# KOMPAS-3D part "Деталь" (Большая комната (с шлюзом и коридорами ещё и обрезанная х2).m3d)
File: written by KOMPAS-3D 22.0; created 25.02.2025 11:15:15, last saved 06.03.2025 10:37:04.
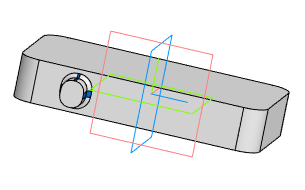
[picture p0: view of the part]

Document properties: Автор: Пользователь Windows; Полное имя файла: C:\Users\Student\Documents\Картошечка\База Сабнатика\Большая комната\Большая комната (с шлюзом и коридорами ещё и обрезанная х2).m3d

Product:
- Part/product: Деталь
    Масса: 1.391303

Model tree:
1. Эскиз:1
2. Элемент выдавливания:1
     Расстояние 1 = 35
3. Скругление:2  (with: Элемент выдавливания:1)
     Радиус = 10
4. Скругление:1  (with: Элемент выдавливания:1)
     Радиус = 7
5. Эскиз:4  (with: Элемент выдавливания:1)
6. Элемент выдавливания:4
     Расстояние 1 = 10
7. Скругление:6  (with: Элемент выдавливания:4)
     Радиус = 2
8. Эскиз:5  (with: Элемент выдавливания:1)
9. Элемент выдавливания:5
     Расстояние 1 = 10
10. Скругление:7  (with: Элемент выдавливания:5)
     Радиус = 2
11. Эскиз:6  (with: Элемент выдавливания:1)
12. Элемент выдавливания:6
     Расстояние 2 = 7
13. Эскиз:7  (with: Элемент выдавливания:1)
14. Элемент выдавливания:7
     Расстояние 2 = 7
